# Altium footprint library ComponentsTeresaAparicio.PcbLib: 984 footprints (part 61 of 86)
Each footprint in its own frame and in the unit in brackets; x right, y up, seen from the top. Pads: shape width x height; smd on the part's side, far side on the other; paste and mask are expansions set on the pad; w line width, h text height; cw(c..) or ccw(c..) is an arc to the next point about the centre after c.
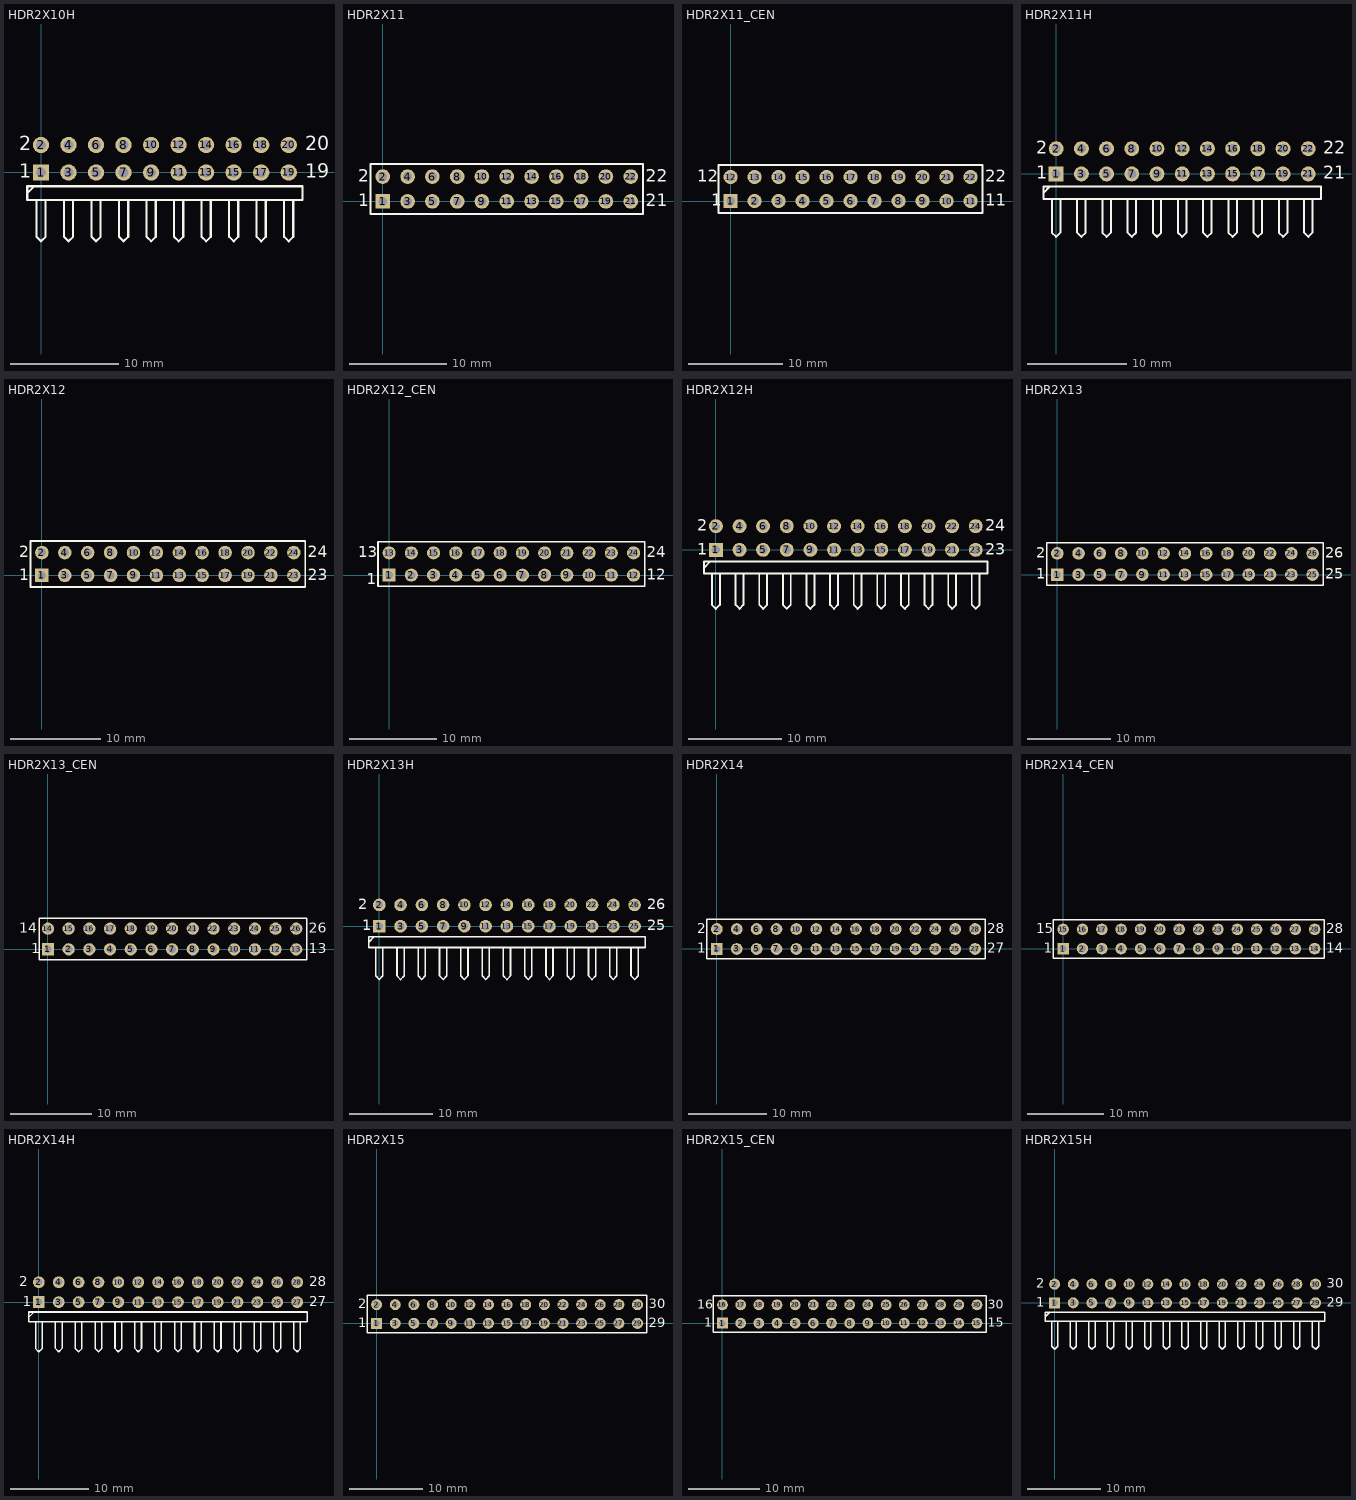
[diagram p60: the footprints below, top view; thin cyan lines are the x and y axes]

## HDR2X10H [mm] "Connector; Header; 10x2 Position; Right Angle"
pads (20):
  rect 1.5x1.5 hole 0.9: 1(0,0)
  round 1.5 hole 0.9: 2(0,2.54) 3(2.54,0) 4(2.54,2.54) 5(5.08,0) 6(5.08,2.54) 7(7.62,0) 8(7.62,2.54) 9(10.16,0) 10(10.16,2.54) 11(12.7,0) 12(12.7,2.54) 13(15.24,0) 14(15.24,2.54) 15(17.78,0) 16(17.78,2.54) 17(20.32,0) 18(20.32,2.54) 19(22.86,0) 20(22.86,2.54)
Top Overlay:
  lines w0.2: -1.27,-1.905 -0.635,-1.27 ; -0.423,-2.54 -0.423,-5.927 0,-6.35 0.423,-5.927 0.423,-2.54 ; 2.117,-2.54 2.117,-5.927 2.54,-6.35 2.963,-5.927 2.963,-2.54 ; 4.657,-2.54 4.657,-5.927 5.08,-6.35 5.503,-5.927 5.503,-2.54 ; 7.197,-2.54 7.197,-5.927 7.62,-6.35 8.043,-5.927 8.043,-2.54 ; 9.737,-2.54 9.737,-5.927 10.16,-6.35 10.583,-5.927 10.583,-2.54 ; 12.277,-2.54 12.277,-5.927 12.7,-6.35 13.123,-5.927 13.123,-2.54 ; 14.817,-2.54 14.817,-5.927 15.24,-6.35 15.663,-5.927 15.663,-2.54 ; 17.357,-2.54 17.357,-5.927 17.78,-6.35 18.203,-5.927 18.203,-2.54 ; 19.897,-2.54 19.897,-5.927 20.32,-6.35 20.743,-5.927 20.743,-2.54 ; 22.437,-2.54 22.437,-5.927 22.86,-6.35 23.283,-5.927 23.283,-2.54 ; -1.27,-2.54 24.13,-2.54 24.13,-1.27 -1.27,-1.27 -1.27,-2.54
  text "20" at 24.384,2.032 h1.27
  text "19" at 24.384,-0.508 h1.27
  text "2" at -2.032,2.032 h1.27
  text "1" at -2.032,-0.508 h1.27

## HDR2X11 [mm] "Connector; Header; 11x2 Position"
pads (22):
  rect 1.5x1.5 hole 0.9: 1(0,0)
  round 1.5 hole 0.9: 2(0,2.54) 3(2.54,0) 4(2.54,2.54) 5(5.08,0) 6(5.08,2.54) 7(7.62,0) 8(7.62,2.54) 9(10.16,0) 10(10.16,2.54) 11(12.7,0) 12(12.7,2.54) 13(15.24,0) 14(15.24,2.54) 15(17.78,0) 16(17.78,2.54) 17(20.32,0) 18(20.32,2.54) 19(22.86,0) 20(22.86,2.54) 21(25.4,0) 22(25.4,2.54)
Top Overlay:
  lines w0.2: -1.27,-1.27 -1.27,3.81 26.67,3.81 26.67,-1.27 -1.27,-1.27
  text "1" at -2.54,-0.508 h1.27
  text "2" at -2.54,2.032 h1.27
  text "21" at 26.924,-0.508 h1.27
  text "22" at 26.924,2.032 h1.27

## HDR2X11_CEN [mm] "Connector; Header; 11x2 Position"
pads (22):
  rect 1.5x1.5 hole 0.9: 1(0,0)
  round 1.5 hole 0.9: 2(2.54,0) 3(5.08,0) 4(7.62,0) 5(10.16,0) 6(12.7,0) 7(15.24,0) 8(17.78,0) 9(20.32,0) 10(22.86,0) 11(25.4,0) 12(0,2.54) 13(2.54,2.54) 14(5.08,2.54) 15(7.62,2.54) 16(10.16,2.54) 17(12.7,2.54) 18(15.24,2.54) 19(17.78,2.54) 20(20.32,2.54) 21(22.86,2.54) 22(25.4,2.54)
Top Overlay:
  lines w0.2: -1.27,-1.27 26.67,-1.27 26.67,3.81 -1.27,3.81 -1.27,-1.27
  text "22" at 26.924,2.032 h1.27
  text "11" at 26.924,-0.508 h1.27
  text "12" at -3.556,2.032 h1.27
  text "1" at -2.032,-0.508 h1.27

## HDR2X11H [mm] "Connector; Header; 11x2 Position; Right Angle"
pads (22):
  rect 1.5x1.5 hole 0.9: 1(0,0)
  round 1.5 hole 0.9: 2(0,2.54) 3(2.54,0) 4(2.54,2.54) 5(5.08,0) 6(5.08,2.54) 7(7.62,0) 8(7.62,2.54) 9(10.16,0) 10(10.16,2.54) 11(12.7,0) 12(12.7,2.54) 13(15.24,0) 14(15.24,2.54) 15(17.78,0) 16(17.78,2.54) 17(20.32,0) 18(20.32,2.54) 19(22.86,0) 20(22.86,2.54) 21(25.4,0) 22(25.4,2.54)
Top Overlay:
  lines w0.2: -1.27,-1.905 -0.635,-1.27 ; -0.423,-2.54 -0.423,-5.927 0,-6.35 0.423,-5.927 0.423,-2.54 ; 2.117,-2.54 2.117,-5.927 2.54,-6.35 2.963,-5.927 2.963,-2.54 ; 4.657,-2.54 4.657,-5.927 5.08,-6.35 5.503,-5.927 5.503,-2.54 ; 7.197,-2.54 7.197,-5.927 7.62,-6.35 8.043,-5.927 8.043,-2.54 ; 9.737,-2.54 9.737,-5.927 10.16,-6.35 10.583,-5.927 10.583,-2.54 ; 12.277,-2.54 12.277,-5.927 12.7,-6.35 13.123,-5.927 13.123,-2.54 ; 14.817,-2.54 14.817,-5.927 15.24,-6.35 15.663,-5.927 15.663,-2.54 ; 17.357,-2.54 17.357,-5.927 17.78,-6.35 18.203,-5.927 18.203,-2.54 ; 19.897,-2.54 19.897,-5.927 20.32,-6.35 20.743,-5.927 20.743,-2.54 ; 22.437,-2.54 22.437,-5.927 22.86,-6.35 23.283,-5.927 23.283,-2.54 ; 24.977,-2.54 24.977,-5.927 25.4,-6.35 25.823,-5.927 25.823,-2.54 ; -1.27,-2.54 -1.27,-1.27 26.67,-1.27 26.67,-2.54 -1.27,-2.54
  text "22" at 26.924,2.032 h1.27
  text "21" at 26.924,-0.508 h1.27
  text "1" at -2.032,-0.508 h1.27
  text "2" at -2.032,2.032 h1.27

## HDR2X12 [mm] "Connector; Header; 12x2 Position"
pads (24):
  rect 1.5x1.5 hole 0.9: 1(0,0)
  round 1.5 hole 0.9: 2(0,2.54) 3(2.54,0) 4(2.54,2.54) 5(5.08,0) 6(5.08,2.54) 7(7.62,0) 8(7.62,2.54) 9(10.16,0) 10(10.16,2.54) 11(12.7,0) 12(12.7,2.54) 13(15.24,0) 14(15.24,2.54) 15(17.78,0) 16(17.78,2.54) 17(20.32,0) 18(20.32,2.54) 19(22.86,0) 20(22.86,2.54) 21(25.4,0) 22(25.4,2.54) 23(27.94,0) 24(27.94,2.54)
Top Overlay:
  lines w0.2: -1.27,-1.27 29.21,-1.27 29.21,3.81 -1.27,3.81 -1.27,-1.27
  text "24" at 29.464,2.032 h1.27
  text "23" at 29.464,-0.508 h1.27
  text "2" at -2.54,2.032 h1.27
  text "1" at -2.54,-0.508 h1.27

## HDR2X12_CEN [mm] "Connector; Header; 12x2 Position"
pads (24):
  rect 1.5x1.5 hole 0.9: 1(0,0)
  round 1.5 hole 0.9: 2(2.54,0) 3(5.08,0) 4(7.62,0) 5(10.16,0) 6(12.7,0) 7(15.24,0) 8(17.78,0) 9(20.32,0) 10(22.86,0) 11(25.4,0) 12(27.94,0) 13(0,2.54) 14(2.54,2.54) 15(5.08,2.54) 16(7.62,2.54) 17(10.16,2.54) 18(12.7,2.54) 19(15.24,2.54) 20(17.78,2.54) 21(20.32,2.54) 22(22.86,2.54) 23(25.4,2.54) 24(27.94,2.54)
Top Overlay:
  lines w0.2: -1.27,-1.27 -1.27,3.81 29.21,3.81 29.21,-1.27 -1.27,-1.27
  text "24" at 29.464,2.032 h1.27
  text "12" at 29.464,-0.508 h1.27
  text "13" at -3.556,2.032 h1.27
  text "1" at -2.54,-1.016 h1.27

## HDR2X12H [mm] "Connector; Header; 12x2 Position; Right Angle"
pads (24):
  rect 1.5x1.5 hole 0.9: 1(0,0)
  round 1.5 hole 0.9: 2(0,2.54) 3(2.54,0) 4(2.54,2.54) 5(5.08,0) 6(5.08,2.54) 7(7.62,0) 8(7.62,2.54) 9(10.16,0) 10(10.16,2.54) 11(12.7,0) 12(12.7,2.54) 13(15.24,0) 14(15.24,2.54) 15(17.78,0) 16(17.78,2.54) 17(20.32,0) 18(20.32,2.54) 19(22.86,0) 20(22.86,2.54) 21(25.4,0) 22(25.4,2.54) 23(27.94,0) 24(27.94,2.54)
Top Overlay:
  lines w0.2: -1.27,-1.905 -0.635,-1.27 ; -0.423,-2.54 -0.423,-5.927 0,-6.35 0.423,-5.927 0.423,-2.54 ; 2.117,-2.54 2.117,-5.927 2.54,-6.35 2.963,-5.927 2.963,-2.54 ; 4.657,-2.54 4.657,-5.927 5.08,-6.35 5.503,-5.927 5.503,-2.54 ; 7.197,-2.54 7.197,-5.927 7.62,-6.35 8.043,-5.927 8.043,-2.54 ; 9.737,-2.54 9.737,-5.927 10.16,-6.35 10.583,-5.927 10.583,-2.54 ; 12.277,-2.54 12.277,-5.927 12.7,-6.35 13.123,-5.927 13.123,-2.54 ; 14.817,-2.54 14.817,-5.927 15.24,-6.35 15.663,-5.927 15.663,-2.54 ; 17.357,-2.54 17.357,-5.927 17.78,-6.35 18.203,-5.927 18.203,-2.54 ; 19.897,-2.54 19.897,-5.927 20.32,-6.35 20.743,-5.927 20.743,-2.54 ; 22.437,-2.54 22.437,-5.927 22.86,-6.35 23.283,-5.927 23.283,-2.54 ; 24.977,-2.54 24.977,-5.927 25.4,-6.35 25.823,-5.927 25.823,-2.54 ; 27.517,-2.54 27.517,-5.927 27.94,-6.35 28.363,-5.927 28.363,-2.54 ; -1.27,-2.54 -1.27,-1.27 29.21,-1.27 29.21,-2.54 -1.27,-2.54
  text "24" at 28.956,2.032 h1.27
  text "23" at 28.956,-0.508 h1.27
  text "2" at -2.032,2.032 h1.27
  text "1" at -2.032,-0.508 h1.27

## HDR2X13 [mm] "Connector; Header; 13x2 Position"
pads (26):
  rect 1.5x1.5 hole 0.9: 1(0,0)
  round 1.5 hole 0.9: 2(0,2.54) 3(2.54,0) 4(2.54,2.54) 5(5.08,0) 6(5.08,2.54) 7(7.62,0) 8(7.62,2.54) 9(10.16,0) 10(10.16,2.54) 11(12.7,0) 12(12.7,2.54) 13(15.24,0) 14(15.24,2.54) 15(17.78,0) 16(17.78,2.54) 17(20.32,0) 18(20.32,2.54) 19(22.86,0) 20(22.86,2.54) 21(25.4,0) 22(25.4,2.54) 23(27.94,0) 24(27.94,2.54) 25(30.48,0) 26(30.48,2.54)
Top Overlay:
  lines w0.2: -1.27,-1.27 31.75,-1.27 31.75,3.81 -1.27,3.81 -1.27,-1.27
  text "26" at 32.004,2.032 h1.27
  text "25" at 32.004,-0.508 h1.27
  text "1" at -2.54,-0.508 h1.27
  text "2" at -2.54,2.032 h1.27

## HDR2X13_CEN [mm] "Connector; Header; 13x2 Position"
pads (26):
  rect 1.5x1.5 hole 0.9: 1(0,0)
  round 1.5 hole 0.9: 2(2.54,0) 3(5.08,0) 4(7.62,0) 5(10.16,0) 6(12.7,0) 7(15.24,0) 8(17.78,0) 9(20.32,0) 10(22.86,0) 11(25.4,0) 12(27.94,0) 13(30.48,0) 14(0,2.54) 15(2.54,2.54) 16(5.08,2.54) 17(7.62,2.54) 18(10.16,2.54) 19(12.7,2.54) 20(15.24,2.54) 21(17.78,2.54) 22(20.32,2.54) 23(22.86,2.54) 24(25.4,2.54) 25(27.94,2.54) 26(30.48,2.54)
Top Overlay:
  lines w0.2: -1.058,-1.27 31.75,-1.27 31.75,3.81 -1.058,3.81 -1.058,-1.27
  text "1" at -2.032,-0.508 h1.27
  text "14" at -3.556,2.032 h1.27
  text "13" at 32.004,-0.508 h1.27
  text "26" at 32.004,2.032 h1.27

## HDR2X13H [mm] "Connector; Header; 13x2 Position; Right Angle"
pads (26):
  rect 1.5x1.5 hole 0.9: 1(0,0)
  round 1.5 hole 0.9: 2(0,2.54) 3(2.54,0) 4(2.54,2.54) 5(5.08,0) 6(5.08,2.54) 7(7.62,0) 8(7.62,2.54) 9(10.16,0) 10(10.16,2.54) 11(12.7,0) 12(12.7,2.54) 13(15.24,0) 14(15.24,2.54) 15(17.78,0) 16(17.78,2.54) 17(20.32,0) 18(20.32,2.54) 19(22.86,0) 20(22.86,2.54) 21(25.4,0) 22(25.4,2.54) 23(27.94,0) 24(27.94,2.54) 25(30.48,0) 26(30.48,2.54)
Top Overlay:
  lines w0.2: -1.27,-1.905 -0.635,-1.27 ; -0.423,-2.54 -0.423,-5.927 0,-6.35 0.423,-5.927 0.423,-2.54 ; 2.117,-2.54 2.117,-5.927 2.54,-6.35 2.963,-5.927 2.963,-2.54 ; 4.657,-2.54 4.657,-5.927 5.08,-6.35 5.503,-5.927 5.503,-2.54 ; 7.197,-2.54 7.197,-5.927 7.62,-6.35 8.043,-5.927 8.043,-2.54 ; 9.737,-2.54 9.737,-5.927 10.16,-6.35 10.583,-5.927 10.583,-2.54 ; 12.277,-2.54 12.277,-5.927 12.7,-6.35 13.123,-5.927 13.123,-2.54 ; 14.817,-2.54 14.817,-5.927 15.24,-6.35 15.663,-5.927 15.663,-2.54 ; 17.357,-2.54 17.357,-5.927 17.78,-6.35 18.203,-5.927 18.203,-2.54 ; 19.897,-2.54 19.897,-5.927 20.32,-6.35 20.743,-5.927 20.743,-2.54 ; 22.437,-2.54 22.437,-5.927 22.86,-6.35 23.283,-5.927 23.283,-2.54 ; 24.977,-2.54 24.977,-5.927 25.4,-6.35 25.823,-5.927 25.823,-2.54 ; 27.517,-2.54 27.517,-5.927 27.94,-6.35 28.363,-5.927 28.363,-2.54 ; 30.057,-2.54 30.057,-5.927 30.48,-6.35 30.903,-5.927 30.903,-2.54 ; -1.27,-2.54 31.75,-2.54 31.75,-1.27 -1.27,-1.27 -1.27,-2.54
  text "2" at -2.54,2.032 h1.27
  text "1" at -2.032,-0.508 h1.27
  text "25" at 32.004,-0.508 h1.27
  text "26" at 32.004,2.032 h1.27

## HDR2X14 [mm] "Connector; Header; 14x2 Position"
pads (28):
  rect 1.5x1.5 hole 0.9: 1(0,0)
  round 1.5 hole 0.9: 2(0,2.54) 3(2.54,0) 4(2.54,2.54) 5(5.08,0) 6(5.08,2.54) 7(7.62,0) 8(7.62,2.54) 9(10.16,0) 10(10.16,2.54) 11(12.7,0) 12(12.7,2.54) 13(15.24,0) 14(15.24,2.54) 15(17.78,0) 16(17.78,2.54) 17(20.32,0) 18(20.32,2.54) 19(22.86,0) 20(22.86,2.54) 21(25.4,0) 22(25.4,2.54) 23(27.94,0) 24(27.94,2.54) 25(30.48,0) 26(30.48,2.54) 27(33.02,0) 28(33.02,2.54)
Top Overlay:
  lines w0.2: -1.27,-1.27 34.29,-1.27 34.29,3.81 -1.27,3.81 -1.27,-1.27
  text "28" at 34.544,2.032 h1.27
  text "27" at 34.544,-0.508 h1.27
  text "1" at -2.54,-0.508 h1.27
  text "2" at -2.54,2.032 h1.27

## HDR2X14_CEN [mm] "Connector; Header; 14x2 Position"
pads (28):
  rect 1.5x1.5 hole 0.9: 1(0,0)
  round 1.5 hole 0.9: 2(2.54,0) 3(5.08,0) 4(7.62,0) 5(10.16,0) 6(12.7,0) 7(15.24,0) 8(17.78,0) 9(20.32,0) 10(22.86,0) 11(25.4,0) 12(27.94,0) 13(30.48,0) 14(33.02,0) 15(0,2.54) 16(2.54,2.54) 17(5.08,2.54) 18(7.62,2.54) 19(10.16,2.54) 20(12.7,2.54) 21(15.24,2.54) 22(17.78,2.54) 23(20.32,2.54) 24(22.86,2.54) 25(25.4,2.54) 26(27.94,2.54) 27(30.48,2.54) 28(33.02,2.54)
Top Overlay:
  lines w0.2: -1.27,-1.27 34.29,-1.27 34.29,3.81 -1.27,3.81 -1.27,-1.27
  text "15" at -3.556,2.032 h1.27
  text "1" at -2.54,-0.508 h1.27
  text "14" at 34.544,-0.508 h1.27
  text "28" at 34.544,2.032 h1.27

## HDR2X14H [mm] "Connector; Header; 14x2 Position; Right Angle"
pads (28):
  rect 1.5x1.5 hole 0.9: 1(0,0)
  round 1.5 hole 0.9: 2(0,2.54) 3(2.54,0) 4(2.54,2.54) 5(5.08,0) 6(5.08,2.54) 7(7.62,0) 8(7.62,2.54) 9(10.16,0) 10(10.16,2.54) 11(12.7,0) 12(12.7,2.54) 13(15.24,0) 14(15.24,2.54) 15(17.78,0) 16(17.78,2.54) 17(20.32,0) 18(20.32,2.54) 19(22.86,0) 20(22.86,2.54) 21(25.4,0) 22(25.4,2.54) 23(27.94,0) 24(27.94,2.54) 25(30.48,0) 26(30.48,2.54) 27(33.02,0) 28(33.02,2.54)
Top Overlay:
  lines w0.2: -1.27,-1.905 -0.635,-1.27 ; -0.423,-2.54 -0.423,-5.927 0,-6.35 0.423,-5.927 0.423,-2.54 ; 2.117,-2.54 2.117,-5.927 2.54,-6.35 2.963,-5.927 2.963,-2.54 ; 4.657,-2.54 4.657,-5.927 5.08,-6.35 5.503,-5.927 5.503,-2.54 ; 7.197,-2.54 7.197,-5.927 7.62,-6.35 8.043,-5.927 8.043,-2.54 ; 9.737,-2.54 9.737,-5.927 10.16,-6.35 10.583,-5.927 10.583,-2.54 ; 12.277,-2.54 12.277,-5.927 12.7,-6.35 13.123,-5.927 13.123,-2.54 ; 14.817,-2.54 14.817,-5.927 15.24,-6.35 15.663,-5.927 15.663,-2.54 ; 17.357,-2.54 17.357,-5.927 17.78,-6.35 18.203,-5.927 18.203,-2.54 ; 19.897,-2.54 19.897,-5.927 20.32,-6.35 20.743,-5.927 20.743,-2.54 ; 22.437,-2.54 22.437,-5.927 22.86,-6.35 23.283,-5.927 23.283,-2.54 ; 24.977,-2.54 24.977,-5.927 25.4,-6.35 25.823,-5.927 25.823,-2.54 ; 27.517,-2.54 27.517,-5.927 27.94,-6.35 28.363,-5.927 28.363,-2.54 ; 30.057,-2.54 30.057,-5.927 30.48,-6.35 30.903,-5.927 30.903,-2.54 ; 32.597,-2.54 32.597,-5.927 33.02,-6.35 33.443,-5.927 33.443,-2.54 ; -1.27,-2.54 -1.27,-1.27 34.29,-1.27 34.29,-2.54 -1.27,-2.54
  text "28" at 34.544,2.032 h1.27
  text "27" at 34.544,-0.508 h1.27
  text "1" at -2.032,-0.508 h1.27
  text "2" at -2.54,2.032 h1.27

## HDR2X15 [mm] "Connector; Header; 15x2 Position"
pads (30):
  rect 1.5x1.5 hole 0.9: 1(0,0)
  round 1.5 hole 0.9: 2(0,2.54) 3(2.54,0) 4(2.54,2.54) 5(5.08,0) 6(5.08,2.54) 7(7.62,0) 8(7.62,2.54) 9(10.16,0) 10(10.16,2.54) 11(12.7,0) 12(12.7,2.54) 13(15.24,0) 14(15.24,2.54) 15(17.78,0) 16(17.78,2.54) 17(20.32,0) 18(20.32,2.54) 19(22.86,0) 20(22.86,2.54) 21(25.4,0) 22(25.4,2.54) 23(27.94,0) 24(27.94,2.54) 25(30.48,0) 26(30.48,2.54) 27(33.02,0) 28(33.02,2.54) 29(35.56,0) 30(35.56,2.54)
Top Overlay:
  lines w0.2: -1.27,-1.27 -1.27,3.81 36.83,3.81 36.83,-1.27 -1.27,-1.27
  text "30" at 37.084,2.032 h1.27
  text "29" at 37.084,-0.508 h1.27
  text "2" at -2.54,2.032 h1.27
  text "1" at -2.54,-0.508 h1.27

## HDR2X15_CEN [mm] "Connector; Header; 15x2 Position"
pads (30):
  rect 1.5x1.5 hole 0.9: 1(0,0)
  round 1.5 hole 0.9: 2(2.54,0) 3(5.08,0) 4(7.62,0) 5(10.16,0) 6(12.7,0) 7(15.24,0) 8(17.78,0) 9(20.32,0) 10(22.86,0) 11(25.4,0) 12(27.94,0) 13(30.48,0) 14(33.02,0) 15(35.56,0) 16(0,2.54) 17(2.54,2.54) 18(5.08,2.54) 19(7.62,2.54) 20(10.16,2.54) 21(12.7,2.54) 22(15.24,2.54) 23(17.78,2.54) 24(20.32,2.54) 25(22.86,2.54) 26(25.4,2.54) 27(27.94,2.54) 28(30.48,2.54) 29(33.02,2.54) 30(35.56,2.54)
Top Overlay:
  lines w0.2: -1.27,-1.27 -1.27,3.81 36.83,3.81 36.83,-1.27 -1.27,-1.27
  text "16" at -3.556,2.032 h1.27
  text "1" at -2.54,-0.508 h1.27
  text "15" at 37.084,-0.508 h1.27
  text "30" at 37.084,2.032 h1.27

## HDR2X15H [mm] "Connector; Header; 15x2 Position; Right Angle"
pads (30):
  rect 1.5x1.5 hole 0.9: 1(0,0)
  round 1.5 hole 0.9: 2(0,2.54) 3(2.54,0) 4(2.54,2.54) 5(5.08,0) 6(5.08,2.54) 7(7.62,0) 8(7.62,2.54) 9(10.16,0) 10(10.16,2.54) 11(12.7,0) 12(12.7,2.54) 13(15.24,0) 14(15.24,2.54) 15(17.78,0) 16(17.78,2.54) 17(20.32,0) 18(20.32,2.54) 19(22.86,0) 20(22.86,2.54) 21(25.4,0) 22(25.4,2.54) 23(27.94,0) 24(27.94,2.54) 25(30.48,0) 26(30.48,2.54) 27(33.02,0) 28(33.02,2.54) 29(35.56,0) 30(35.56,2.54)
Top Overlay:
  lines w0.2: -1.27,-1.905 -0.635,-1.27 ; -0.423,-2.54 -0.423,-5.927 0,-6.35 0.423,-5.927 0.423,-2.54 ; 2.117,-2.54 2.117,-5.927 2.54,-6.35 2.963,-5.927 2.963,-2.54 ; 4.657,-2.54 4.657,-5.927 5.08,-6.35 5.503,-5.927 5.503,-2.54 ; 7.197,-2.54 7.197,-5.927 7.62,-6.35 8.043,-5.927 8.043,-2.54 ; 9.737,-2.54 9.737,-5.927 10.16,-6.35 10.583,-5.927 10.583,-2.54 ; 12.277,-2.54 12.277,-5.927 12.7,-6.35 13.123,-5.927 13.123,-2.54 ; 14.817,-2.54 14.817,-5.927 15.24,-6.35 15.663,-5.927 15.663,-2.54 ; 17.357,-2.54 17.357,-5.927 17.78,-6.35 18.203,-5.927 18.203,-2.54 ; 19.897,-2.54 19.897,-5.927 20.32,-6.35 20.743,-5.927 20.743,-2.54 ; 22.437,-2.54 22.437,-5.927 22.86,-6.35 23.283,-5.927 23.283,-2.54 ; 24.977,-2.54 24.977,-5.927 25.4,-6.35 25.823,-5.927 25.823,-2.54 ; 27.517,-2.54 27.517,-5.927 27.94,-6.35 28.363,-5.927 28.363,-2.54 ; 30.057,-2.54 30.057,-5.927 30.48,-6.35 30.903,-5.927 30.903,-2.54 ; 32.597,-2.54 32.597,-5.927 33.02,-6.35 33.443,-5.927 33.443,-2.54 ; 35.137,-2.54 35.137,-5.927 35.56,-6.35 35.983,-5.927 35.983,-2.54 ; -1.27,-2.54 36.83,-2.54 36.83,-1.27 -1.27,-1.27 -1.27,-2.54
  text "2" at -2.54,2.032 h1.27
  text "1" at -2.54,-0.508 h1.27
  text "29" at 37.084,-0.508 h1.27
  text "30" at 37.084,2.032 h1.27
